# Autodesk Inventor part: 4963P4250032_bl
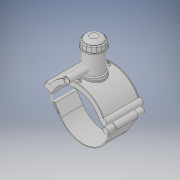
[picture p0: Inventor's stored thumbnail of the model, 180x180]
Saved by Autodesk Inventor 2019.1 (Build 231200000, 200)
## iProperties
Created: 2017-07
Part Number: 4963P4250032_bl
Material: Generic
Document SubType Name: Modeling
Designer: KIM
Density: 1 g/cm^3
Appearance: Default
Author: KIM
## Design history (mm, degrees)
derived "4963P4.ipt"
feature "Solid1::4963P4.ipt" dims "ScaleForDerivedMember" = 10
feature "Solid2::4963P4.ipt" dims "ScaleForDerivedMember" = 10
feature "Solid3::4963P4.ipt" dims "ScaleForDerivedMember" = 10
tag "TaggingFeature1"
body "Solid1"
body "Solid2"
body "Solid3"
other parameters: "d2" = 327.6 [user parameter], "d3" = 62.5 [user parameter], "d4" = 176 [user parameter], "d5" = 0 [user parameter], "d6" = 0.1 [user parameter], "d8" = 0 [user parameter], "d19" = 6 [user parameter], "d20" = 6 [user parameter], "d21" = 105.6 [user parameter], "d23" = 0 [user parameter], "d24" = 52.8 [user parameter], "d26" = 0 [user parameter], "d27" = 3 [user parameter], "d28" = 3 [user parameter], "d29" = 3 [user parameter], "d30" = 83.33333 [user parameter], "d31" = 6 [user parameter], "d32" = 0 [user parameter], "d33" = 0 [user parameter], "d34" = 0.6 [user parameter], "d40" = 150.8 [user parameter], "d43" = 0 [user parameter], "d45" = 0 [user parameter], "d47" = 250.6 [user parameter], "d70" = 15 [user parameter], "d72" = 0 [user parameter], "d73" = 6 [user parameter], "d75" = 5 [user parameter], "d76" = 0 [user parameter], "d77" = 12.5 [user parameter], "d78" = 155 [user parameter], "d79" = 15 [user parameter], "d80" = 70.4 [user parameter], "d82" = 5 deg [user parameter], "d84" = 4 [user parameter], "d85" = 14 [user parameter], "d86" = 0 [user parameter], "d87" = 3 [user parameter], "d88" = 0 [user parameter], "d89" = 1 [user parameter], "d90" = 1 [user parameter], "d91" = 140.8 [user parameter], "d92" = 0 [user parameter], "d93" = 0.5 [user parameter], "d94" = 131.57895 [user parameter], "d96" = 295.8 [user parameter], "d97" = 3.52 [user parameter], "d98" = 0 [user parameter], "d102" = 2.5 [user parameter], "d120" = 140 deg [user parameter], "d121" = 24.228 [user parameter], "d122" = 20 deg [user parameter], "d124" = 174 [user parameter], "d126" = 0 [user parameter], "d143" = 257.5 [user parameter], "d145" = 30.76923 [user parameter], "d149" = 3.75 [user parameter], "d150" = 33.84615 [user parameter], "d153" = 176 [user parameter], "d154" = 0 [user parameter], "d156" = 145 [user parameter], "d157" = 160 deg [user parameter], "d159" = 8 [user parameter], "d161" = 3.75 [user parameter], "d162" = 105.6 [user parameter], "d163" = 0 [user parameter], "d164" = 125 [user parameter], "d167" = 25 [user parameter], "d168" = 141.46341 [user parameter], "d170" = 3.75 [user parameter], "d172" = 0 [user parameter], "d173" = 1 [user parameter], "d175" = 125 [user parameter], "d176" = 20 deg [user parameter], "d177" = 17.5 [user parameter], "d180" = 0 [user parameter], "d183" = 16 [user parameter], "d184" = 14 [user parameter], "d185" = 57.2 [user parameter], "d186" = 57.2 [user parameter], "d187" = 145 [user parameter], "d188" = 12 [user parameter], "d189" = 17.5 [user parameter], "d190" = 0 [user parameter], "d191" = 217.5 [user parameter], "d193" = 8 [user parameter], "d194" = 6.16 [user parameter], "d195" = 90 deg [user parameter], "d197" = 0 [user parameter], "d199" = 0 [user parameter], "d202" = 0 [user parameter], "d203" = 177 [user parameter], "d204" = 95 [user parameter], "d206" = 85 [user parameter], "d207" = 132.75 [user parameter], "d208" = 138.06 [user parameter], "d209" = 164.61 [user parameter], "d210" = 86 [user parameter], "d213" = 36 [user parameter], "d216" = 0 [user parameter], "d217" = 25 [user parameter], "d218" = 25 [user parameter], "d219" = 5 [user parameter], "d224" = 0 [user parameter], "d225" = 56 [user parameter], "d226" = 32 [user parameter], "d227" = 25.6 [user parameter], "d228" = 132 [user parameter], "d230" = 5 [user parameter], "B_" = 252 [user parameter], "L_" = 176 [user parameter], "d_t" = 6 [user parameter], "H_2" = 177 [user parameter], "H_1" = 56 [user parameter], "d_1" = 32 [user parameter], "H_" = 132 [user parameter], "d148" = 3.75 [user parameter], "d160" = 3.75 [user parameter], "d169" = 3.75 [user parameter], "d192" = 8 [user parameter]
